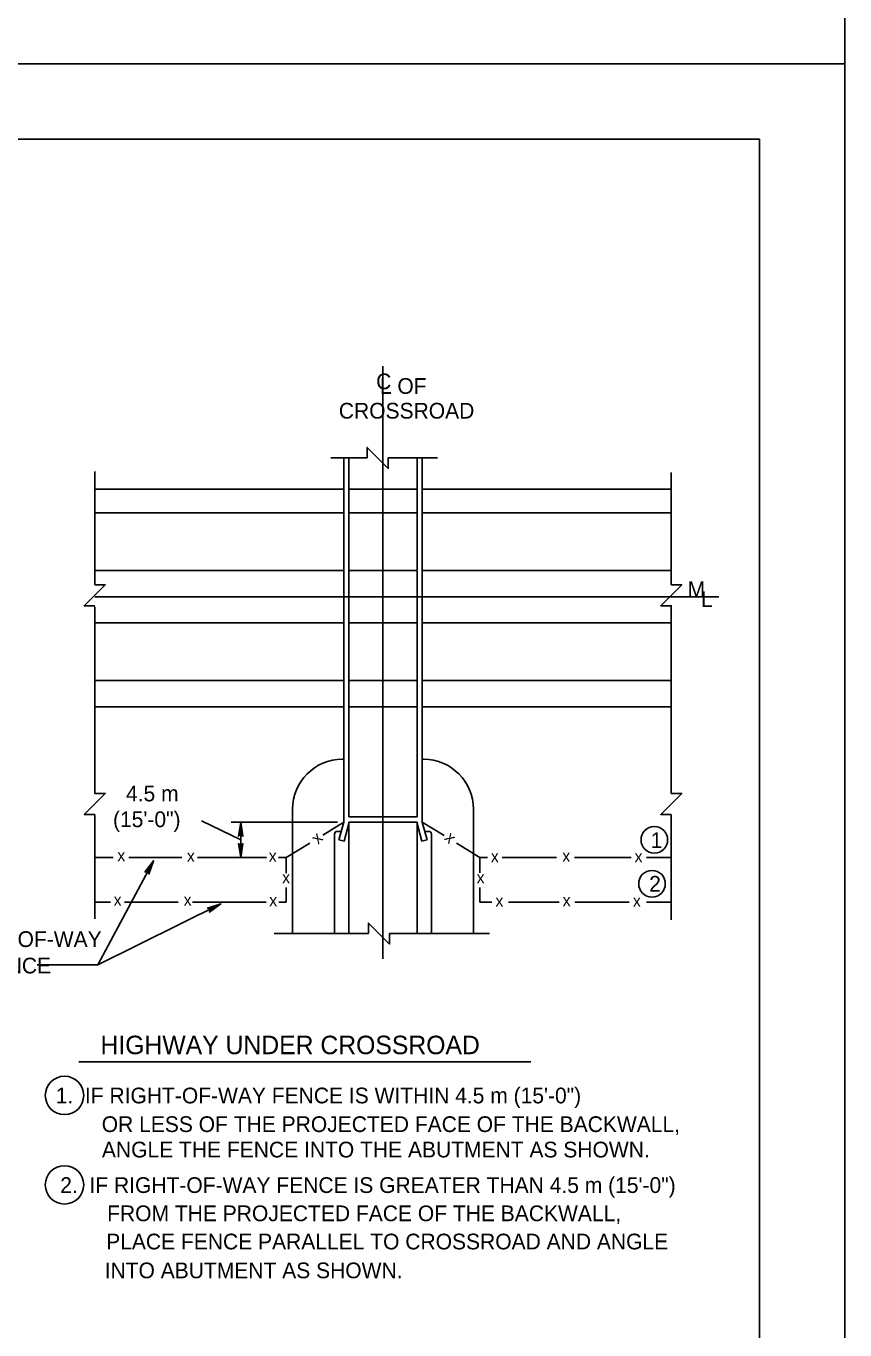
# Model space of a CAD drawing. Extents: x 13 to 918, y -903 to 879.
# Drawn here: x 691.5 to 854.3, y -560.6 to -301.6 of the extents above; entities that cross this region are included whole.
import ezdxf

# ---------------------------------------------------------------- set-up
doc = ezdxf.new("R2010")
doc.units = 0
for name, color, linetype in [('1', 7, 'Continuous'), ('3', 7, 'Continuous'), ('PLT-BNDY', 7, 'Continuous')]:
    doc.layers.add(name, color=color, linetype=linetype)

msp = doc.modelspace()

# ---------------------------------------------------------------- linework, layer by layer
at = {"layer": '1'}
for points in [[(837.2505, -888.06975), (837.2505, -324.06975), (51.2505, -324.06975), (51.2505, -888.06975), (837.2505, -888.06975), (837.2505, -861.71075), (637.2505, -861.71075), (637.2505, -797.03325), (837.2505, -797.03325), (837.2505, -768.06975), (637.2505, -768.06975), (637.2505, -888.06975), (716.052, -888.06975), (716.052, -861.71075), (716.052, -888.06975), (793.052, -888.06975), (793.052, -861.71075), (793.052, -874.02725), (837.2505, -874.02725)], [(715.29325, -469.5755), (715.51, -469.57975), (716.837, -467.3985), (715.29325, -469.5755), (715.1265, -469.64225), (716.837, -467.3985), (715.74525, -469.70475), (715.86825, -469.8755), (716.837, -467.3985), (715.912, -470.063), (715.86825, -469.8755)], [(727.70575, -476.85675), (727.87875, -476.984), (730.2265, -475.97975), (727.70575, -476.85675), (727.53275, -476.813), (730.2265, -475.97975), (727.9995, -477.2235), (727.9995, -477.434), (730.2265, -475.97975), (727.9265, -477.611), (727.9995, -477.434)]]:
    msp.add_lwpolyline(points, dxfattribs=at)
at = {"layer": '3'}
for p, q in [((762.439, -369.136), (762.439, -486.8735)), ((759.314, -387.35475), (752.05375, -387.35475)), ((754.6265, -387.35475), (754.6265, -459.7485)), ((755.66825, -387.35475), (755.66825, -458.70675)), ((773.2995, -387.35475), (763.48075, -387.35475)), ((769.21, -387.35475), (769.21, -409.68175)), ((770.2515, -387.35475), (770.2515, -409.68175)), ((705.1475, -412.561), (705.1475, -390.08175)), ((819.73075, -412.561), (819.73075, -390.2505)), ((754.614, -393.60475), (705.1475, -393.60475)), ((769.189, -393.60475), (755.6975, -393.60475)), ((819.73075, -393.60475), (770.25375, -393.60475)), ((754.63275, -398.29225), (705.1475, -398.29225)), ((769.28275, -398.29225), (755.66, -398.29225)), ((819.73075, -398.29225), (770.25375, -398.29225)), ((754.6515, -409.7505), (705.1475, -409.7505)), ((769.2265, -409.7505), (755.67875, -409.7505)), ((769.21, -409.7755), (769.21, -420.184)), ((770.2515, -409.7005), (770.2515, -459.7485)), ((819.73075, -409.7505), (770.25375, -409.7505)), ((829.17025, -414.959), (705.1475, -414.959)), ((705.1475, -454.0215), (705.1475, -416.9505)), ((819.73075, -454.0215), (819.73075, -416.61525)), ((754.63275, -420.16525), (705.1475, -420.16525)), ((769.3015, -420.16525), (755.67875, -420.16525)), ((769.21, -420.20275), (769.21, -431.58175)), ((819.73075, -420.16525), (770.1225, -420.16525)), ((754.63275, -431.6235), (705.1475, -431.6235)), ((769.2265, -431.6235), (755.64125, -431.6235)), ((769.21, -431.638), (769.21, -436.7965)), ((819.73075, -431.6235), (770.25375, -431.6235)), ((754.63275, -436.83175), (705.1475, -436.83175)), ((769.3015, -436.83175), (755.64125, -436.83175)), ((769.21, -436.81525), (769.21, -458.70675)), ((819.73075, -436.83175), (770.44125, -436.83175)), ((754.63275, -447.2485), (754.36625, -447.2485)), ((770.512, -447.2485), (770.32875, -447.2485)), ((705.1475, -478.96925), (705.1475, -458.188)), ((744.47025, -457.14425), (744.47025, -481.884)), ((780.40775, -457.14425), (780.40775, -481.884)), ((819.73075, -479.138), (819.73075, -458.188)), ((734.15575, -463.263), (726.362, -459.4985)), ((753.38075, -459.7485), (732.26625, -459.7485)), ((734.15575, -459.7485), (734.15575, -466.77975)), ((750.45775, -462.30675), (754.6265, -459.7485)), ((754.6265, -459.7485), (753.68275, -463.26925)), ((755.63275, -460.01925), (754.689, -463.538)), ((769.21, -458.70675), (755.66825, -458.70675)), ((769.21, -459.7485), (755.66825, -459.7485)), ((755.66825, -459.7485), (755.66825, -481.884)), ((769.21, -459.7485), (769.21, -481.884)), ((770.189, -463.538), (769.24525, -460.01925)), ((771.19525, -463.26925), (770.2515, -459.7485)), ((774.564, -462.39425), (770.2515, -459.7485)), ((752.80375, -462.09425), (752.80375, -481.884)), ((754.137, -461.5735), (753.3245, -461.5735)), ((753.68275, -463.26925), (754.689, -463.538)), ((771.19525, -463.26925), (770.189, -463.538)), ((771.55375, -461.5735), (770.74125, -461.5735)), ((772.0745, -462.09425), (772.0745, -481.884)), ((743.16825, -466.77975), (747.87875, -463.89025)), ((781.71, -466.77975), (777.035, -463.911)), ((708.7975, -466.77975), (705.1475, -466.77975)), ((716.837, -467.3985), (705.75775, -488.088)), ((722.45575, -466.77975), (711.8995, -466.77975)), ((739.2725, -466.77975), (725.539, -466.77975)), ((743.16825, -466.77975), (741.6475, -466.77975)), ((743.16825, -466.77975), (743.16825, -469.86925)), ((783.2225, -466.77975), (781.71, -466.77975)), ((781.71, -466.77975), (781.71, -469.79425)), ((796.95575, -466.77975), (786.137, -466.77975)), ((811.79325, -466.77975), (800.50575, -466.77975)), ((819.73075, -466.77975), (814.8015, -466.77975)), ((743.16825, -472.69025), (743.16825, -475.634)), ((781.71, -472.69025), (781.71, -475.634)), ((708.25575, -475.634), (705.1475, -475.634)), ((730.2265, -475.97975), (705.75775, -488.088)), ((721.7265, -475.634), (711.0765, -475.634)), ((739.1995, -475.634), (724.5495, -475.634)), ((743.16825, -475.634), (741.739, -475.634)), ((784.04325, -475.634), (781.71, -475.634)), ((797.4225, -475.634), (787.40775, -475.634)), ((811.34325, -475.634), (800.5995, -475.634)), ((819.73075, -475.634), (814.8015, -475.634)), ((759.5475, -481.884), (740.8245, -481.884)), ((783.59525, -481.884), (763.714, -481.884)), ((705.75775, -488.088), (693.70575, -488.088)), ((701.967, -507.33825), (791.842, -507.33825))]:
    msp.add_line(p, q, dxfattribs=at)
for points in [[(759.314, -387.35475), (759.314, -385.2715), (763.48075, -389.438), (763.48075, -387.35475)], [(705.1475, -412.561), (707.23075, -412.561), (703.064, -416.72775), (705.1475, -416.72775)], [(819.73075, -412.561), (821.814, -412.561), (817.6475, -416.72775), (819.73075, -416.72775)], [(705.1475, -454.0215), (707.23075, -454.0215), (703.064, -458.188), (705.1475, -458.188)], [(819.73075, -454.0215), (821.814, -454.0215), (817.6475, -458.188), (819.73075, -458.188)], [(733.8225, -462.3965), (734.014, -462.2985), (734.15575, -459.7485), (733.8225, -462.3965), (733.70775, -462.534), (734.15575, -459.7485), (734.28075, -462.2965), (734.4725, -462.39025), (734.15575, -459.7485), (734.5975, -462.534), (734.4725, -462.39025)], [(734.489, -464.13175), (734.2975, -464.22975), (734.15575, -466.77975), (734.489, -464.13175), (734.60375, -463.99425), (734.15575, -466.77975), (734.03075, -464.23175), (733.839, -464.138), (734.15575, -466.77975), (733.714, -463.99425), (733.839, -464.138)], [(759.5475, -481.884), (759.5475, -479.8005), (763.714, -483.96725), (763.714, -481.884)]]:
    msp.add_lwpolyline(points, dxfattribs=at)
for centre, radius in [((816.37039, -463.24533), 2.64645), ((815.90164, -471.97033), 2.64645), ((699.13487, -514.03375), 3.81089), ((699.13487, -531.7975), 3.81089)]:
    msp.add_circle(centre, radius, dxfattribs=at)
for centre, radius, start, end in [((754.36539, -457.14346), 9.895, 90, 180), ((770.51289, -457.14346), 9.895, 0, 90), ((753.32372, -462.09346), 0.52, 90, 180), ((771.55456, -462.09346), 0.52, 0, 90)]:
    msp.add_arc(centre, radius, start, end, dxfattribs=at)
at = {"layer": 'PLT-BNDY'}
for points in [[(13.2505, 284.93025), (854.2505, 284.93025), (854.2505, -309.06975), (13.2505, -309.06975)], [(13.2505, -309.06975), (854.2505, -309.06975), (854.2505, -903.06975), (13.2505, -903.06975)]]:
    msp.add_lwpolyline(points, close=True, dxfattribs=at)

# ---------------------------------------------------------------- texts
at = {"layer": '1'}
for s, height, p in [('RIGHT-OF-WAY', 3.1249995, (675.42025, -484.54025)), ('FENCE', 3.124999, (682.30775, -489.79025))]:
    msp.add_text(s, height=height, dxfattribs=at).set_placement(p)
at = {"layer": '3'}
for s, height, p in [('C', 3.125, (761.0725, -373.7255)), ('L OF', 3.124999, (761.814, -374.64025)), ('CROSSROAD', 3.124999, (753.65775, -379.55475)), ('M', 3.125, (822.98275, -415.038)), ('L', 3.125, (825.635, -417.01725)), ('4.5 m', 3.124999, (711.35875, -455.60225)), ('(15\'-0")', 3.124999, (708.772, -460.72725)), ('1', 3.125, (815.63075, -464.89225)), ('x', 2.34584, (709.637, -467.51925)), ('x', 2.34584, (723.464, -467.613)), ('x', 2.34584, (739.739, -467.613)), ('x', 2.34584, (783.8745, -467.70675)), ('x', 2.34584, (798.0765, -467.613)), ('x', 2.34584, (812.44525, -467.70675)), ('x', 2.34584, (742.39325, -471.89225)), ('x', 2.34584, (781.05375, -471.89225)), ('2', 3.125, (815.34125, -473.54225)), ('x', 2.34584, (708.90775, -476.34025)), ('x', 2.34584, (722.82875, -476.34025)), ('x', 2.34584, (739.83275, -476.43175)), ('x', 2.34584, (784.79125, -476.5255)), ('x', 2.34584, (798.1515, -476.43175)), ('x', 2.34375, (812.11, -476.54025)), ('HIGHWAY UNDER CROSSROAD', 3.6770865, (706.28575, -505.83825)), ('1.  IF RIGHT-OF-WAY FENCE IS WITHIN 4.5 m (15\'-0") ', 3.1249995, (697.388, -515.607)), ('OR LESS OF THE PROJECTED FACE OF THE BACKWALL,', 3.1249995, (706.53575, -521.30375)), ('ANGLE THE FENCE INTO THE ABUTMENT AS SHOWN.', 3.1249995, (706.56825, -526.3505)), ('2.  IF RIGHT-OF-WAY FENCE IS GREATER THAN 4.5 m (15\'-0")', 3.1249995, (698.292, -533.409)), ('FROM THE PROJECTED FACE OF THE BACKWALL,', 3.1249995, (707.60475, -539.015)), ('PLACE FENCE PARALLEL TO CROSSROAD AND ANGLE', 3.1249995, (707.417, -544.6215)), ('INTO ABUTMENT AS SHOWN.', 3.1249995, (707.117, -550.35475))]:
    msp.add_text(s, height=height, dxfattribs=at).set_placement(p)
for height, rotation, p in [(2.34449, 45.0551444, (749.56825, -464.24225)), (2.34301, 315, (774.49525, -463.05475))]:
    msp.add_text('x', height=height, rotation=rotation, dxfattribs=at).set_placement(p)

doc.saveas('drawing.dxf')
